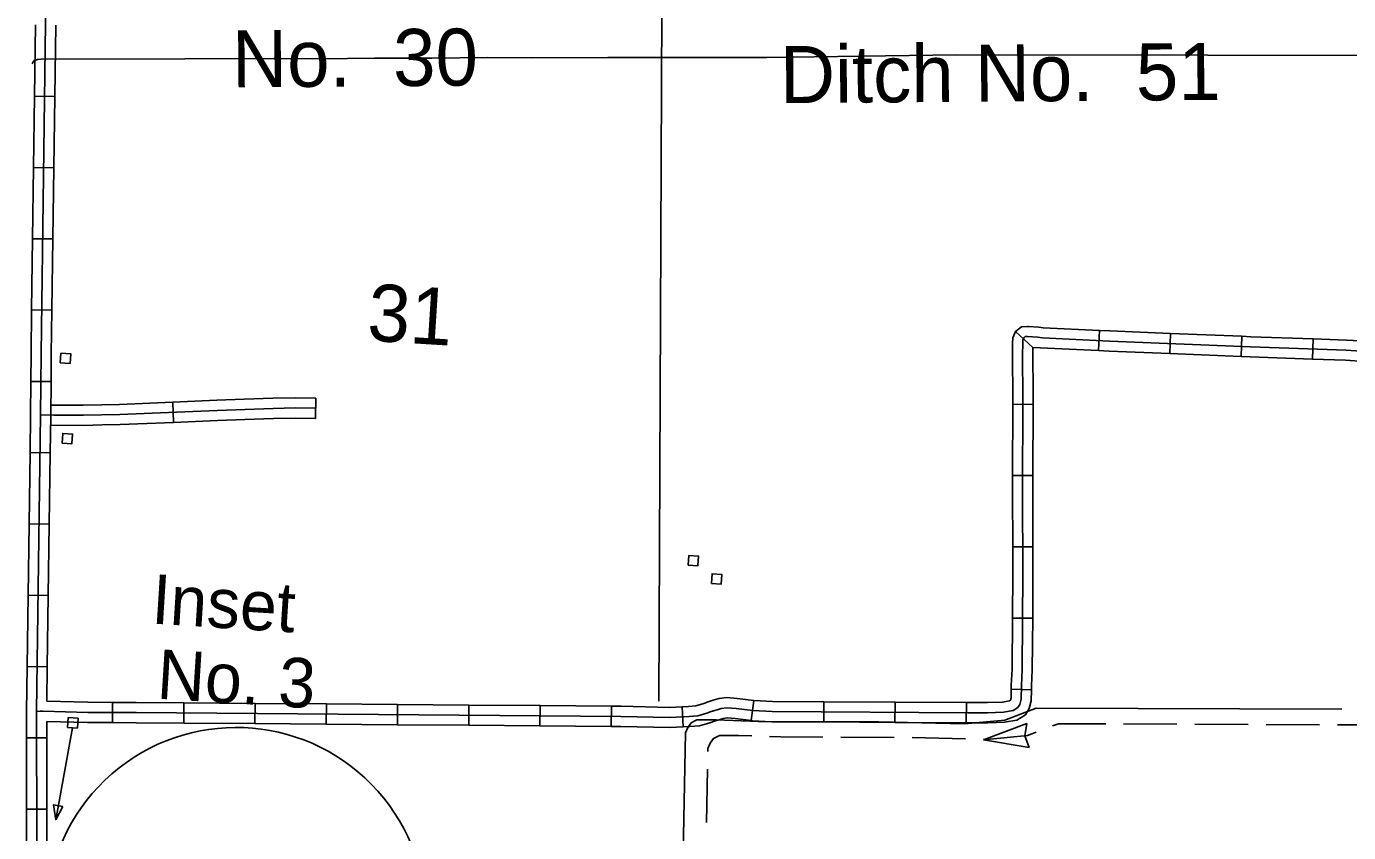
# Model space of a CAD drawing. Extents: x 1366406 to 1373462, y 376856 to 381998.
# Drawn here: x 1369440.1 to 1369598.7, y 380098.9 to 380195.6 of the extents above; entities that cross this region are included whole.
import ezdxf

# ---------------------------------------------------------------- set-up
doc = ezdxf.new("R2010")
doc.units = 0
for name, color, linetype in [('32', 7, 'Continuous'), ('43', 7, 'Continuous'), ('45', 7, 'Continuous'), ('5', 7, 'Continuous'), ('56', 7, 'Continuous'), ('63', 7, 'Continuous')]:
    doc.layers.add(name, color=color, linetype=linetype)

msp = doc.modelspace()

# ---------------------------------------------------------------- linework, layer by layer
at = {"layer": '32'}
for p, q in [((1369441.05, 380187.22), (1369443.48, 380187.19)), ((1369440.93, 380178.67), (1369443.36, 380178.64)), ((1369440.82, 380170.12), (1369443.25, 380170.09)), ((1369440.7, 380161.57), (1369443.13, 380161.53)), ((1369558.76, 380158.99), (1369560.84, 380157.07)), ((1369568.86, 380159.13), (1369568.74, 380156.7)), ((1369577.39, 380158.77), (1369577.29, 380156.34)), ((1369585.94, 380158.42), (1369585.84, 380155.99)), ((1369594.48, 380158.11), (1369594.4, 380155.68)), ((1369440.6, 380153.01), (1369443.03, 380152.99)), ((1369558.45, 380150.26), (1369560.88, 380150.25)), ((1369440.51, 380144.46), (1369442.94, 380144.43)), ((1369558.42, 380141.71), (1369560.85, 380141.7)), ((1369440.39, 380135.91), (1369442.82, 380135.87)), ((1369558.44, 380133.14), (1369560.87, 380133.15)), ((1369440.27, 380127.35), (1369442.7, 380127.32)), ((1369558.41, 380124.6), (1369560.84, 380124.59)), ((1369440.16, 380118.8), (1369442.58, 380118.77)), ((1369527.37, 380114.72), (1369527.07, 380112.31)), ((1369535.78, 380114.58), (1369535.76, 380112.15)), ((1369558.26, 380116.07), (1369560.69, 380116.01)), ((1369450.41, 380114.5), (1369450.4, 380112.07)), ((1369458.96, 380114.45), (1369458.95, 380112.02)), ((1369467.52, 380114.38), (1369467.5, 380111.95)), ((1369476.07, 380114.31), (1369476.05, 380111.88)), ((1369484.62, 380114.25), (1369484.61, 380111.82)), ((1369493.18, 380114.18), (1369493.16, 380111.75)), ((1369501.73, 380114.11), (1369501.71, 380111.68)), ((1369510.28, 380114.05), (1369510.27, 380111.62)), ((1369518.77, 380113.98), (1369518.88, 380111.55)), ((1369544.33, 380114.52), (1369544.31, 380112.09)), ((1369552.88, 380114.47), (1369552.87, 380112.04)), ((1369440.08, 380110.23), (1369442.51, 380110.23)), ((1369440.09, 380101.68), (1369442.52, 380101.68))]:
    msp.add_line(p, q, dxfattribs=at)
for points in [[(1369443.17, 380281.29), (1369442.94, 380259.58), (1369442.76, 380233.54), (1369442.42, 380199.08), (1369441.85, 380156.3), (1369441.78, 380148.99), (1369441.3, 380113.39), (1369441.31, 380097.83), (1369441.25, 380072.65), (1369441.2, 380069.82)], [(1369441.16, 380195.78), (1369441.05, 380187.22)], [(1369443.59, 380195.74), (1369443.48, 380187.19)], [(1369852.65, 380192.36), (1369849.2, 380192.29), (1369788.77, 380192.18), (1369731.07, 380192.44), (1369727.44, 380192.43), (1369671.5, 380192.32), (1369668.52, 380192.31), (1369612.02, 380192.11), (1369551.71, 380192.18), (1369528.92, 380191.88), (1369521.37, 380191.87), (1369509.84, 380191.86), (1369500.83, 380191.83), (1369495.4, 380191.85), (1369488.72, 380191.8), (1369481.86, 380191.8), (1369475.38, 380191.72), (1369469.8, 380191.73), (1369459.1, 380191.69), (1369441.85, 380191.65), (1369441.4, 380191.62), (1369441.02, 380191.5), (1369440.89, 380191.36), (1369440.75, 380191.09)], [(1369441.05, 380187.22), (1369440.93, 380178.67)], [(1369443.48, 380187.19), (1369443.36, 380178.64)], [(1369440.93, 380178.67), (1369440.82, 380170.12)], [(1369443.36, 380178.64), (1369443.25, 380170.09)], [(1369440.82, 380170.12), (1369440.7, 380161.57)], [(1369443.25, 380170.09), (1369443.13, 380161.53)], [(1369440.7, 380161.57), (1369440.63, 380156.31), (1369440.6, 380153.01)], [(1369443.13, 380161.53), (1369443.06, 380156.28), (1369443.03, 380152.99)], [(1369560.35, 380159.6), (1369560.22, 380159.61), (1369559.48, 380159.57), (1369558.76, 380158.99), (1369558.44, 380158.23), (1369558.42, 380157.56), (1369558.42, 380156.2), (1369558.45, 380151), (1369558.45, 380150.26)], [(1369568.86, 380159.13), (1369562.1, 380159.44), (1369561.58, 380159.51), (1369560.35, 380159.6)], [(1369577.39, 380158.77), (1369570.1, 380159.07), (1369568.86, 380159.13)], [(1369600.77, 380156.61), (1369598.44, 380156.75), (1369586.98, 380157.16), (1369570.05, 380157.85), (1369562, 380158.23), (1369561.47, 380158.3), (1369560.21, 380158.39), (1369559.94, 380158.38), (1369559.76, 380158.23), (1369559.65, 380157.97), (1369559.64, 380157.54), (1369559.63, 380156.2), (1369559.67, 380151.01), (1369559.63, 380139.64), (1369559.66, 380129.98), (1369559.58, 380118.43), (1369559.49, 380116.51), (1369559.45, 380114.87), (1369559.28, 380114.25), (1369559.07, 380113.89), (1369558.48, 380113.51), (1369557.33, 380113.33), (1369555.43, 380113.26), (1369553.07, 380113.25), (1369529.57, 380113.4), (1369527.27, 380113.51), (1369525.27, 380113.76), (1369524.15, 380113.85), (1369523.45, 380113.77), (1369522.97, 380113.62), (1369522.26, 380113.4), (1369521.73, 380113.21), (1369520.64, 380112.9), (1369519.61, 380112.8), (1369517.26, 380112.69), (1369511.43, 380112.82), (1369453.25, 380113.28), (1369447.43, 380113.3), (1369442.07, 380113.45), (1369441.73, 380113.45), (1369441.3, 380113.39)], [(1369585.94, 380158.42), (1369577.39, 380158.77)], [(1369594.48, 380158.11), (1369587.03, 380158.37), (1369585.94, 380158.42)], [(1369603.27, 380157.39), (1369602.39, 380157.63), (1369600.88, 380157.82), (1369598.5, 380157.97), (1369594.48, 380158.11)], [(1369560.84, 380157.07), (1369560.88, 380151.01), (1369560.88, 380150.25)], [(1369568.74, 380156.7), (1369560.84, 380157.07)], [(1369577.29, 380156.34), (1369570, 380156.64), (1369568.74, 380156.7)], [(1369585.84, 380155.99), (1369577.29, 380156.34)], [(1369594.4, 380155.68), (1369586.94, 380155.94), (1369585.84, 380155.99)], [(1369602.62, 380155.04), (1369601.92, 380155.24), (1369600.65, 380155.4), (1369598.38, 380155.54), (1369594.4, 380155.68)], [(1369440.6, 380153.01), (1369440.57, 380149), (1369440.51, 380144.46)], [(1369443.03, 380152.99), (1369443, 380148.97), (1369442.94, 380144.43)], [(1369558.45, 380150.26), (1369558.42, 380141.71)], [(1369560.88, 380150.25), (1369560.85, 380141.7)], [(1369440.51, 380144.46), (1369440.39, 380135.91)], [(1369442.94, 380144.43), (1369442.82, 380135.87)], [(1369558.42, 380141.71), (1369558.42, 380139.64), (1369558.44, 380133.14)], [(1369560.85, 380141.7), (1369560.85, 380139.64), (1369560.87, 380133.15)], [(1369440.39, 380135.91), (1369440.27, 380127.35)], [(1369442.82, 380135.87), (1369442.7, 380127.32)], [(1369558.44, 380133.14), (1369558.44, 380129.98), (1369558.41, 380124.6)], [(1369560.87, 380133.15), (1369560.87, 380129.98), (1369560.84, 380124.59)], [(1369440.27, 380127.35), (1369440.16, 380118.8)], [(1369442.7, 380127.32), (1369442.58, 380118.77)], [(1369558.41, 380124.6), (1369558.36, 380118.47), (1369558.27, 380116.56), (1369558.26, 380116.07)], [(1369560.84, 380124.59), (1369560.79, 380118.4), (1369560.7, 380116.47), (1369560.69, 380116.01)], [(1369440.16, 380118.8), (1369440.08, 380113.39), (1369440.08, 380110.23)], [(1369442.58, 380118.77), (1369442.53, 380114.65)], [(1369450.41, 380114.5), (1369447.44, 380114.51), (1369442.53, 380114.65)], [(1369527.37, 380114.72), (1369525.39, 380114.97), (1369524.13, 380115.07), (1369523.21, 380114.96), (1369522.62, 380114.79), (1369521.88, 380114.56), (1369521.36, 380114.37), (1369520.41, 380114.1), (1369519.52, 380114.01), (1369518.77, 380113.98)], [(1369535.78, 380114.58), (1369529.6, 380114.61), (1369527.38, 380114.72), (1369527.37, 380114.72)], [(1369544.33, 380114.52), (1369535.78, 380114.58)], [(1369560.69, 380116.01), (1369560.66, 380114.7), (1369560.41, 380113.78), (1369559.97, 380113.02), (1369558.92, 380112.35), (1369557.45, 380112.12), (1369555.46, 380112.05), (1369553.07, 380112.04), (1369552.87, 380112.04)], [(1369558.26, 380116.07), (1369558.24, 380115.05), (1369558.16, 380114.75), (1369558.04, 380114.67), (1369557.21, 380114.54), (1369555.41, 380114.48), (1369553.07, 380114.47), (1369552.88, 380114.47)], [(1369458.96, 380114.45), (1369453.26, 380114.49), (1369450.41, 380114.5)], [(1369467.52, 380114.38), (1369458.96, 380114.45)], [(1369476.07, 380114.31), (1369467.52, 380114.38)], [(1369484.62, 380114.25), (1369476.07, 380114.31)], [(1369493.18, 380114.18), (1369484.62, 380114.25)], [(1369501.73, 380114.11), (1369493.18, 380114.18)], [(1369510.28, 380114.05), (1369501.73, 380114.11)], [(1369518.77, 380113.98), (1369517.25, 380113.9), (1369511.45, 380114.04), (1369510.28, 380114.05)], [(1369552.88, 380114.47), (1369544.33, 380114.52)], [(1369442.51, 380112.22), (1369442.51, 380110.23)], [(1369450.4, 380112.07), (1369447.41, 380112.08), (1369442.51, 380112.22)], [(1369458.95, 380112.02), (1369453.24, 380112.06), (1369450.4, 380112.07)], [(1369467.5, 380111.95), (1369458.95, 380112.02)], [(1369476.05, 380111.88), (1369467.5, 380111.95)], [(1369484.61, 380111.82), (1369476.05, 380111.88)], [(1369493.16, 380111.75), (1369484.61, 380111.82)], [(1369501.71, 380111.68), (1369493.16, 380111.75)], [(1369510.27, 380111.62), (1369501.71, 380111.68)], [(1369518.88, 380111.55), (1369517.28, 380111.47), (1369511.41, 380111.61), (1369510.27, 380111.62)], [(1369527.07, 380112.31), (1369525.14, 380112.55), (1369524.18, 380112.63), (1369523.7, 380112.57), (1369523.32, 380112.46), (1369522.65, 380112.25), (1369522.1, 380112.05), (1369520.87, 380111.7), (1369519.7, 380111.59), (1369518.88, 380111.55)], [(1369535.76, 380112.15), (1369529.53, 380112.18), (1369527.16, 380112.3), (1369527.07, 380112.31)], [(1369544.31, 380112.09), (1369535.76, 380112.15)], [(1369552.87, 380112.04), (1369544.31, 380112.09)], [(1369440.08, 380110.23), (1369440.09, 380101.68)], [(1369442.51, 380110.23), (1369442.52, 380101.68)], [(1369440.09, 380101.68), (1369440.09, 380097.83), (1369440.08, 380093.13)], [(1369442.52, 380101.68), (1369442.52, 380097.82), (1369442.51, 380093.12)]]:
    msp.add_lwpolyline(points, dxfattribs=at)
at = {"layer": '43'}
for p, q in [((1369554.92, 380110.02), (1369560.13, 380111.95)), ((1369560.13, 380111.95), (1369559.88, 380110.49)), ((1369554.92, 380110.02), (1369560.4, 380109.08)), ((1369560.4, 380109.08), (1369559.88, 380110.47))]:
    msp.add_line(p, q, dxfattribs=at)
for points in [[(1369561.25, 380113.81), (1369557.51, 380112.37), (1369552.67, 380111.93), (1369542.39, 380112.17), (1369527.93, 380112.22), (1369522.87, 380112.4), (1369520.55, 380112.4), (1369519.84, 380112.04), (1369519.45, 380111.49), (1369519.17, 380110.84)], [(1369597.92, 380113.67), (1369561.25, 380113.81)], [(1369569.6, 380111.92), (1369563.94, 380111.94), (1369563.23, 380111.67)], [(1369578.15, 380111.89), (1369571.73, 380111.91)], [(1369586.7, 380111.86), (1369580.29, 380111.88)], [(1369595.26, 380111.82), (1369588.84, 380111.85)], [(1369600.6, 380111.8), (1369597.4, 380111.82)], [(1369519.17, 380110.84), (1369518.17, 380059.27)], [(1369527.12, 380110.47), (1369525.55, 380110.53), (1369523.24, 380110.53), (1369522.53, 380110.18), (1369522.13, 380109.62), (1369521.85, 380108.98), (1369521.85, 380108.62)], [(1369535.67, 380110.33), (1369530.61, 380110.35), (1369529.26, 380110.4)], [(1369544.23, 380110.3), (1369537.81, 380110.32)], [(1369549.57, 380110.2), (1369546.36, 380110.27)], [(1369552.78, 380110.12), (1369549.57, 380110.2)], [(1369561.24, 380110.91), (1369560.2, 380110.51), (1369555.35, 380110.06), (1369554.92, 380110.07)], [(1369521.81, 380106.49), (1369521.68, 380100.07)]]:
    msp.add_lwpolyline(points, dxfattribs=at)
at = {"layer": '45'}
for p, q in [((1369457.63, 380150.52), (1369457.73, 380148.09)), ((1369474.8, 380151), (1369474.76, 380148.57))]:
    msp.add_line(p, q, dxfattribs=at)
for points in [[(1369474.8, 380151), (1369472.32, 380151.04), (1369469.65, 380150.98), (1369466.19, 380150.86)], [(1369474.78, 380149.78), (1369472.32, 380149.82), (1369469.69, 380149.76), (1369462.97, 380149.53), (1369451.28, 380149.04), (1369446.91, 380148.95), (1369443.35, 380148.95), (1369441.78, 380148.99)], [(1369449.11, 380150.21), (1369446.9, 380150.16), (1369443.01, 380150.17)], [(1369457.63, 380150.52), (1369451.24, 380150.25), (1369449.11, 380150.21)], [(1369466.19, 380150.86), (1369462.92, 380150.75), (1369457.63, 380150.52)], [(1369457.73, 380148.09), (1369451.32, 380147.82), (1369449.16, 380147.78)], [(1369466.27, 380148.43), (1369463.01, 380148.32), (1369457.73, 380148.09)], [(1369474.76, 380148.57), (1369472.32, 380148.61), (1369469.72, 380148.55), (1369466.27, 380148.43)], [(1369449.16, 380147.78), (1369446.92, 380147.73), (1369442.98, 380147.74)]]:
    msp.add_lwpolyline(points, dxfattribs=at)
at = {"layer": '5'}
msp.add_lwpolyline([(1369516.34, 380197.7), (1369515.98, 380114.66)], dxfattribs=at)
at = {"layer": '56'}
for points in [[(1369444.14, 380155.22), (1369444.22, 380156.39), (1369445.39, 380156.32), (1369445.31, 380155.15)], [(1369444.36, 380145.59), (1369444.44, 380146.76), (1369445.61, 380146.69), (1369445.54, 380145.52)], [(1369519.5, 380130.95), (1369519.58, 380132.12), (1369520.75, 380132.05), (1369520.67, 380130.88)], [(1369522.29, 380128.76), (1369522.36, 380129.93), (1369523.54, 380129.85), (1369523.46, 380128.68)], [(1369445.02, 380111.5), (1369445.1, 380112.67), (1369446.27, 380112.59), (1369446.2, 380111.42)], [(1369444.46, 380102.01), (1369443.33, 380102.22), (1369443.59, 380100.42)]]:
    msp.add_lwpolyline(points, close=True, dxfattribs=at)
msp.add_lwpolyline([(1369445.61, 380111.46), (1369443.59, 380100.42)], dxfattribs=at)
at = {"layer": '63'}
msp.add_arc((1369465.24, 380088.72), 22.76, 317.9431, 217.3999, dxfattribs=at)

# ---------------------------------------------------------------- texts
at = {"layer": '43'}
for s, height, p in [('No.  30', 6.843, (1369464.78, 380188.28)), ('Ditch No.  51', 6.8429, (1369530.53, 380186.38))]:
    msp.add_text(s, height=height, rotation=0.4306, dxfattribs=at).set_placement(p)
at = {"layer": '5'}
msp.add_text('31', height=6.843, rotation=356.4139, dxfattribs=at).set_placement((1369480.87, 380157.92))
at = {"layer": '63'}
for s, p in [('Inset', (1369454.99, 380123.96)), ('No. 3', (1369455.64, 380114.95))]:
    msp.add_text(s, height=5.94, rotation=356.4139, dxfattribs=at).set_placement(p)

doc.saveas('drawing.dxf')
